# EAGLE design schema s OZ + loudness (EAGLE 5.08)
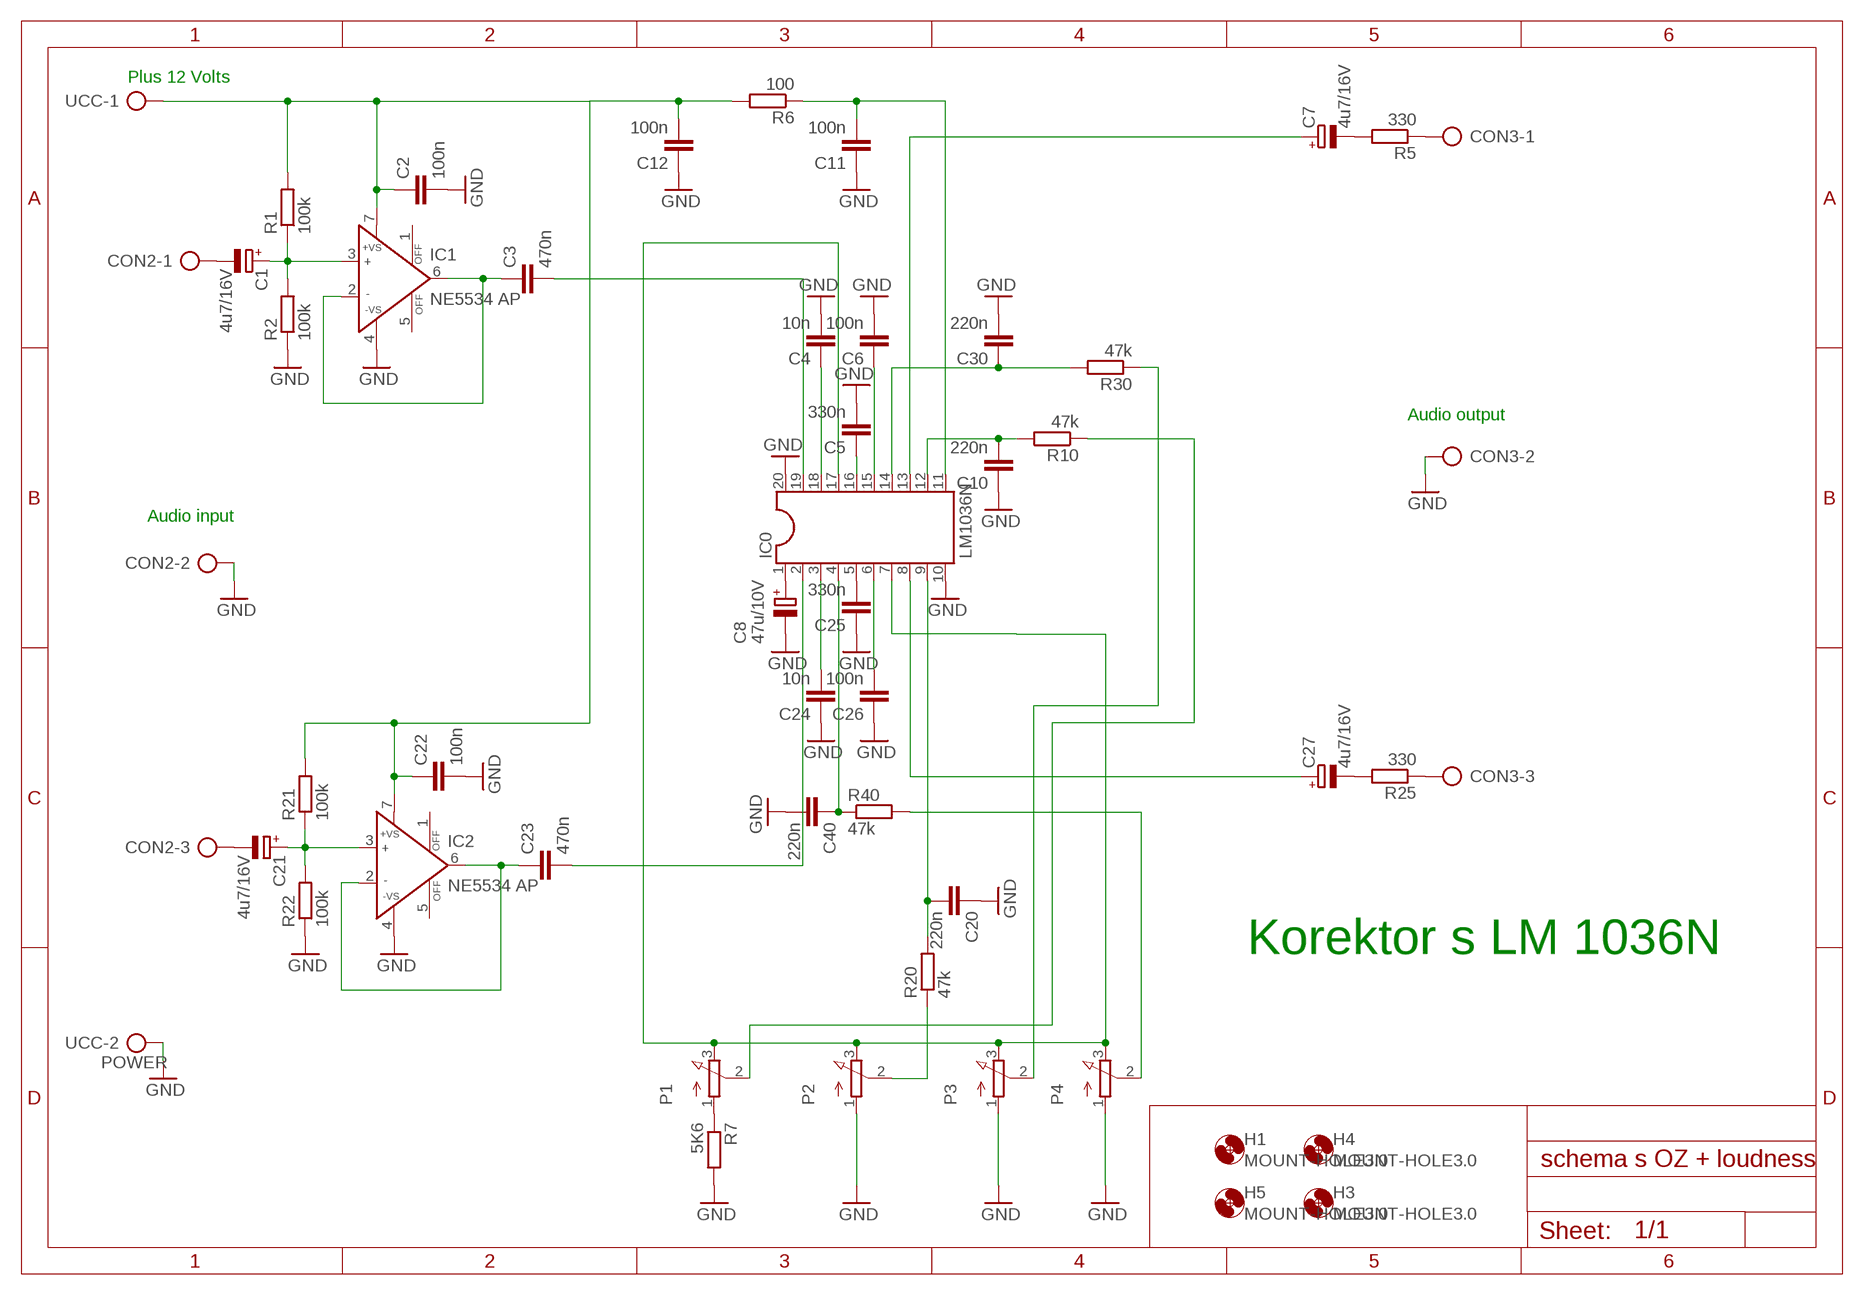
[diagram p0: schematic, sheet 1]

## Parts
C1  4u7/16V  CPOL-EUE2.5-5  [E2,5-5]
C2  100n  C-EU050-025X075  [C050-025X075]
C3  470n  C-EU050-025X075  [C050-025X075]
C4  10n  C-EU050-025X075  [C050-025X075]
C5  330n  C-EU050-025X075  [C050-025X075]
C6  100n  C-EU050-025X075  [C050-025X075]
C7  4u7/16V  CPOL-EUE2.5-5  [E2,5-5]
C8  47u/10V  CPOL-EUE2.5-7  [E2,5-7]
C10  220n  C-EU050-025X075  [C050-025X075]
C11  100n  C-EU050-025X075  [C050-025X075]
C12  100n  C-EU050-025X075  [C050-025X075]
C20  220n  C-EU050-025X075  [C050-025X075]
C21  4u7/16V  CPOL-EUE2.5-5  [E2,5-5]
C22  100n  C-EU050-025X075  [C050-025X075]
C23  470n  C-EU075-032X103  [C075-032X103]
C24  10n  C-EU050-025X075  [C050-025X075]
C25  330n  C-EU050-025X075  [C050-025X075]
C26  100n  C-EU050-025X075  [C050-025X075]
C27  4u7/16V  CPOL-EUE2.5-5  [E2,5-5]
C30  220n  C-EU050-025X075  [C050-025X075]
C40  220n  C-EU050-025X075  [C050-025X075]
CON2  AK500/3  [AK500/3]
CON3  AK500/3  [AK500/3]
H1  MOUNT-HOLE3.0  [3,0]
H3  MOUNT-HOLE3.0  [3,0]
H4  MOUNT-HOLE3.0  [3,0]
H5  MOUNT-HOLE3.0  [3,0]
IC0  LM1036N  DIL20S  [SOCKET-20]
IC1  NE5534 AP  AD711N  [DIL08]
IC2  NE5534 AP  AD711N  [DIL08]
P1  3RP/1610N  [3RP/1610N]
P2  3RP/1610N  [3RP/1610N]
P3  3RP/1610N  [3RP/1610N]
P4  3RP/1610N  [3RP/1610N]
R1  100k  R-EU_0207/10  [0207/10]
R2  100k  R-EU_0207/10  [0207/10]
R5  330  R-EU_0207/10  [0207/10]
R6  100  R-EU_0207/12  [0207/12]
R7  5K6  R-EU_0207/10  [0207/10]
R10  47k  R-EU_0207/12  [0207/12]
R20  47k  R-EU_0207/10  [0207/10]
R21  100k  R-EU_0207/10  [0207/10]
R22  100k  R-EU_0207/10  [0207/10]
R25  330  R-EU_0207/10  [0207/10]
R30  47k  R-EU_0207/12  [0207/12]
R40  47k  R-EU_0207/10  [0207/10]
UCC  POWER  AK500/2  [AK500/2]

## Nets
C25: C26.2 IC0.6
GND: C2.2 C4.2 C5.2 C6.2 C8.- C10.1 C11.1 C12.1 C20.1 C22.2 C24.1 C25.1 C26.1 C30.2 C40.2 CON2.2 CON3.2 IC0.10 IC0.20 IC1.4(-VS) IC2.4(-VS) P2.1(A) P3.1(A) P4.1(A) R2.1 R7.2 R22.1 UCC.2
N$1: C1.- CON2.1
N$2: C3.1 IC1.2(IN-) IC1.6(OUT)
N$3: C23.1 IC2.2(IN-) IC2.6(OUT)
N$4: C1.+ IC1.3(IN+) R1.1 R2.2
N$5: C21.- CON2.3
N$6: C21.+ IC2.3(IN+) R21.1 R22.2
N$7: C2.1 C12.2 C22.1 IC1.7(+VS) IC2.7(+VS) R1.2 R6.2 R21.2 UCC.1
N$8: C3.2 IC0.19
N$9: C23.2 IC0.2
N$10: IC0.17 P1.3(E) P2.3(E) P3.3(E) P4.3(E)
N$11: C11.2 IC0.11 R6.1
N$12: C4.1 IC0.18
N$13: C5.1 IC0.16
N$14: C6.1 IC0.15
N$15: C8.+ IC0.1
N$16: C24.2 IC0.3
N$17: C25.2 IC0.5
N$18: C10.2 IC0.12 R10.2
N$19: P1.1(A) R7.1
N$20: C40.1 IC0.4 R40.1
N$21: P4.2(S) R40.2
N$22: IC0.7
N$23: C7.- R5.2
N$24: C27.- R25.2
N$25: C7.+ IC0.13
N$26: C27.+ IC0.8
N$27: C20.2 IC0.9 R20.2
N$28: P2.2(S) R20.1
N$29: CON3.1 R5.1
N$30: CON3.3 R25.1
N$31: C30.1 IC0.14 R30.2
N$32: P3.2(S) R30.1
N$34: P1.2(S) R10.1
Unconnected: IC1.1(OFF) IC1.5(OFF) IC2.1(OFF) IC2.5(OFF)

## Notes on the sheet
- Plus 12 Volts
- Audio output
- Audio input
- Korektor s LM 1036N

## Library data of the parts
C1 C7 C8 C21 C27 = rcl:CPOL-EU: POLARIZED CAPACITOR, European symbol
C2-C6 C10-C12 C20 C22-C26 C30 C40 = rcl:C-EU: CAPACITOR, European symbol
CON2 CON3 = #Svorkovnice:AK500/3: CONNECTOR
H1 H3-H5 = holes:MOUNT-HOLE: MOUNTING HOLE with drill center marker
IC0 = ic-package:DIL20: Dual In Line / Socket
IC1 IC2 = analog-devices:AD711: Precision, Low Cost, High Speed, BiFET Op Amp Source: http://www.analog.com/static/imported-files/data_sheets/AD711.pdf
P1-P4 = pot:3RP/1610N: 16mm Potentiometer one level Source: http://www.alphapotentiometers.net/html/16mm_pot_2.html
R1 R2 R5-R7 R10 R20-R22 R25 R30 R40 = rcl:R-EU_: RESISTOR, European symbol
UCC = #Svorkovnice:AK500/2: CONNECTOR

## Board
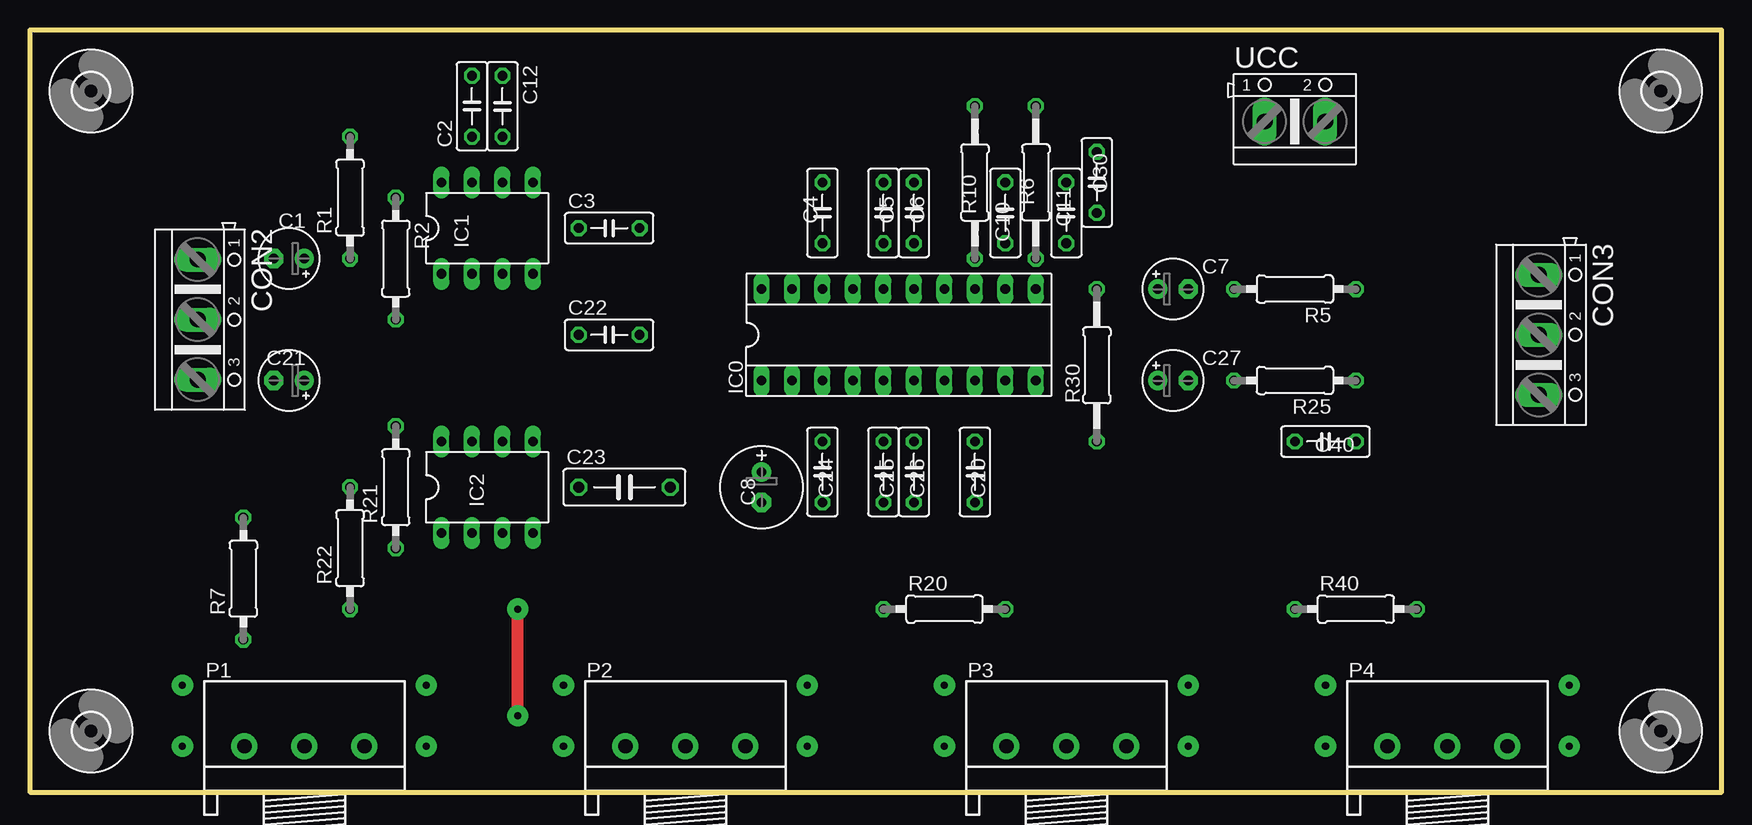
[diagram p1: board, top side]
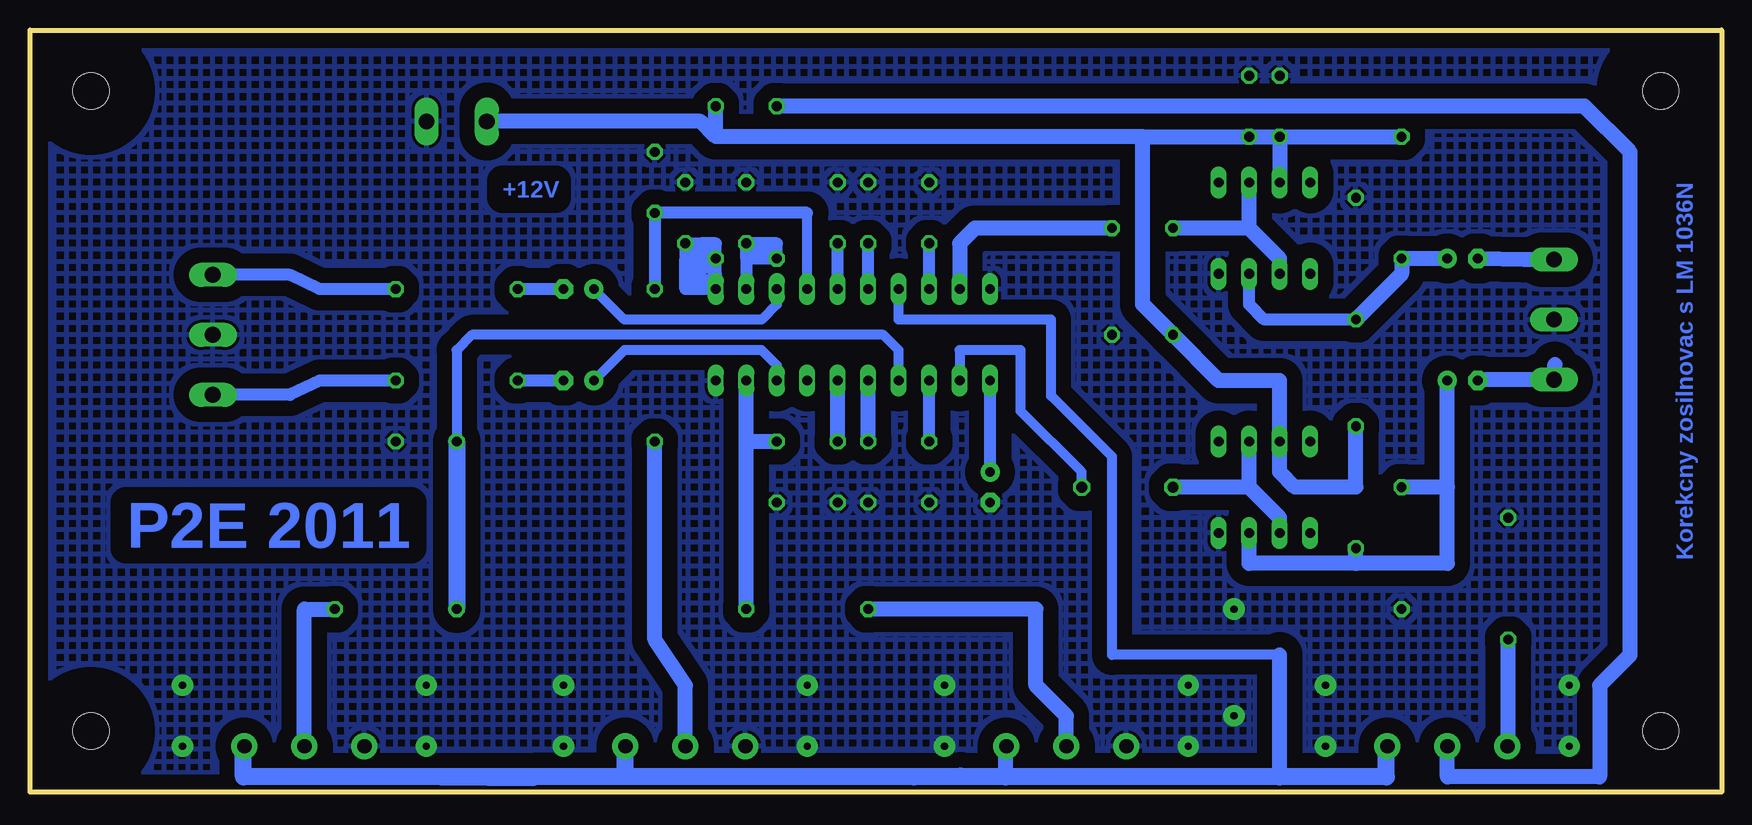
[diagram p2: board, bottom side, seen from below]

Size 140.97 x 63.5 mm. Coordinates in mm from the lower left corner, seen from the top.
Outline: 0,0 140.97,0 140.97,63.5 0,63.5 0,0
Copper layers (1*16): Top 0.035mm / dielectric 1.5mm / Bottom 0.035mm
Design rules "default": minimum track width 10mil, minimum drill 24mil, track to track 8mil, track to pad 8mil, pad to pad 8mil, via to via 8mil, smd to smd 8mil, copper to edge 40mil, drill to drill 8mil, minimum pad ring 10mil, minimum via ring 8mil, stop-mask expansion 4mil, vias tented up to drill 0mil, thermal gap 10mil

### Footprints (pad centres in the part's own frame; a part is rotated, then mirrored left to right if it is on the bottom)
E2,5-5 = drill 0.813 pad 1.6 round: + -1.27,0 | drill 0.813 pad 1.6 octagon: - 1.27,0
C050-025X075 = drill 0.813 octagon: 1 -2.54,0; 2 2.54,0
E2,5-7 = drill 0.813 pad 1.6 round: + -1.27,0 | drill 0.813 pad 1.6 octagon: - 1.27,0
C075-032X103 = drill 0.914 octagon: 1 -3.81,0; 2 3.81,0
AK500/3 = drill 1.321 long: 1 -5.004,0; 2 0,0; 3 5.004,0
3,0 = hole 3: 0,0
SOCKET-20 = drill 0.813 long: 1 -11.43,-3.81; 2 -8.89,-3.81; 3 -6.35,-3.81; 4 -3.81,-3.81; 5 -1.27,-3.81; 6 1.27,-3.81; 7 3.81,-3.81; 8 6.35,-3.81; 9 8.89,-3.81; 10 11.43,-3.81; 11 11.43,3.81; 12 8.89,3.81; 13 6.35,3.81; 14 3.81,3.81; 15 1.27,3.81; 16 -1.27,3.81; 17 -3.81,3.81; 18 -6.35,3.81; 19 -8.89,3.81; 20 -11.43,3.81
DIL08 = drill 0.813 long: 1 -3.81,-3.81; 2 -1.27,-3.81; 3 1.27,-3.81; 4 3.81,-3.81; 5 3.81,3.81; 6 1.27,3.81; 7 -1.27,3.81; 8 -3.81,3.81
3RP/1610N = drill 1.2 pad 2.184 round: 1 -5,0; 2 0,0; 3 5,0
0207/10 = drill 0.813 octagon: 1 -5.08,0; 2 5.08,0
0207/12 = drill 0.813 octagon: 1 -6.35,0; 2 6.35,0
AK500/2 = drill 1.321 long: 1 -2.515,0; 2 2.515,0

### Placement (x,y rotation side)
C1  21.59,44.45 180 top
C2  36.83,57.15 90 top
C3  48.26,46.99 0 top
C4  66.04,48.26 90 top
C5  71.12,48.26 90 top
C6  73.66,48.26 90 top
C7  95.25,41.91 0 top
C8  60.96,25.4 270 top
C10  81.28,48.26 270 top
C11  86.36,48.26 270 top
C12  39.37,57.15 270 top
C20  78.74,26.67 90 top
C21  21.59,34.29 180 top
C22  48.26,38.1 0 top
C23  49.53,25.4 0 top
C24  66.04,26.67 90 top
C25  71.12,26.67 90 top
C26  73.66,26.67 90 top
C27  95.25,34.29 0 top
C30  88.9,50.8 90 top
C40  107.95,29.21 0 top
CON2  13.97,39.37 270 top
CON3  125.73,38.1 270 top
H1  5.08,5.08 0 top
H3  135.89,5.08 0 top
H4  135.89,58.42 0 top
H5  5.08,58.42 0 top
IC0  72.39,38.1 0 top
IC1  38.1,46.99 0 top
IC2  38.1,25.4 0 top
P1  22.86,3.81 0 top
P2  54.61,3.81 0 top
P3  86.36,3.81 0 top
P4  118.11,3.81 0 top
R1  26.67,49.53 90 top
R2  30.48,44.45 270 top
R5  105.41,41.91 180 top
R6  83.82,50.8 90 top
R7  17.78,17.78 90 top
R10  78.74,50.8 270 top
R20  76.2,15.24 0 top
R21  30.48,25.4 90 top
R22  26.67,20.32 90 top
R25  105.41,34.29 180 top
R30  88.9,35.56 90 top
R40  110.49,15.24 0 top
UCC  105.41,55.88 0 top

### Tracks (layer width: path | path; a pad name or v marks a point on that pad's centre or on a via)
C25
  Bottom 1.27: C26.2 IC0.6
GND  (via drill 0.6 pad 1.78)
  Top 1.016: v40.64,6.35 v40.64,15.24
  other vias: 12.7,8.89 12.7,3.81 33.02,8.89 33.02,3.81 44.45,3.81 44.45,8.89 64.77,8.89 64.77,3.81 76.2,3.81 76.2,8.89 96.52,8.89 96.52,3.81 107.95,3.81 107.95,8.89 128.27,8.89 128.27,3.81
  pour Bottom (isolate 1.27, hatched): 0,63.5 0,0 140.97,0 140.97,63.5
N$1
  Bottom 1.27: CON2.1 16.43,44.37 C1.-
N$2
  Bottom 1.27: IC1.2 36.83,44.45 39.37,46.99 | 39.37,46.99 IC1.6 | 39.37,46.99 C3.1
N$3
  Bottom 1.27: IC2.2 36.83,22.86 39.37,25.4 | 39.37,25.4 IC2.6 | 39.37,25.4 C23.1
N$4
  Bottom 1.016: IC1.3 39.37,40.64 38.1,39.37 R2.2
  Bottom 1.27: C1.+ R1.1 26.67,43.18 R2.2
N$5
  Bottom 1.27: 13.89,35.64 CON2.3 20.32,34.37 C21.-
N$6
  Bottom 1.27: IC2.3 39.37,19.05 30.48,19.05 | 30.48,19.05 R21.1 | 30.48,19.05 22.86,19.05 22.86,25.4 | 22.86,25.4 C21.+ | 22.86,25.4 R22.2
N$7
  Bottom 1.27: C2.1 C12.2 48.26,54.61 | C2.1 R1.2 | C2.1 IC1.7 | 48.26,54.61 48.26,40.64 C22.1 41.91,34.29 36.83,34.29 IC2.7 36.83,26.67 35.56,25.4 30.48,25.4 R21.2 | 48.26,54.61 83.82,54.61 | UCC.1 85.09,55.88 83.82,54.61 | 83.82,54.61 R6.2
N$8
  Bottom 1.27: C3.2 62.23,46.99 63.5,45.72 IC0.19
N$9
  Bottom 0.813: IC0.2 63.5,36.83 58.42,36.83 58.42,31.75 53.34,26.67 C23.2
N$10
  Bottom 0.813: IC0.17 68.58,39.37 55.88,39.37 55.88,33.02 50.8,27.94 50.8,11.43 36.83,11.43
  Bottom 1.27: 59.69,1.27 P2.3 | 27.94,3.81 P1.3 | 123.19,3.73 P4.3 | 36.83,1.27 36.83,11.43
  Bottom 1.422: 27.94,3.81 27.94,1.27 36.83,1.27 59.69,1.27 67.31,1.27 | 67.31,1.27 63.42,1.35 | 67.31,1.27 106.68,1.27 | 106.68,1.27 99.06,1.19 | P3.3 91.36,1.35 106.68,1.27 | 106.68,1.27 123.19,1.27 123.19,3.73
N$11
  Bottom 1.016: 83.82,43.18 IC0.11 85.09,41.91 | 83.82,43.18 R6.1 83.82,45.72 | C11.2 85.09,45.72 | 86.36,41.91 86.36,43.18 | 86.36,43.18 86.36,44.45 | C11.2 86.36,44.45 | 85.09,44.45 C11.2 | 83.82,43.18 85.09,44.45 | 83.82,43.18 85.09,41.91 | 85.09,41.91 86.36,41.91 | 86.36,41.91 85.09,43.18 | 86.36,43.18 85.09,43.18 | 85.09,44.45 86.36,43.18 | 85.09,44.45 83.82,45.72 | 83.82,45.72 85.09,45.72 | 86.36,44.45 85.09,45.72 | 85.09,43.18 86.36,44.45
N$12
  Bottom 1.016: IC0.18 C4.1
N$13
  Bottom 1.016: IC0.16 C5.1
N$14
  Bottom 1.016: IC0.15 C6.1
N$15
  Bottom 1.016: C8.+ IC0.1
N$16
  Bottom 1.016: C24.2 IC0.3
N$17
  Bottom 1.27: C25.2 IC0.5
N$18
  Bottom 1.016: 81.28,44.45 IC0.12 | 80.01,44.45 R10.2 78.74,45.72 | 78.74,45.72 80.01,45.72 | 80.01,45.72 C10.2 81.28,44.45 | 80.01,44.45 78.74,45.72 | 80.01,44.45 81.28,44.45 | 80.01,45.72 81.28,44.45
N$19
  Bottom 1.27: R7.1 17.78,3.81 P1.1
N$20
  Bottom 0.813: C40.1 105.41,36.83 104.14,38.1 69.85,38.1 68.58,36.83 IC0.4
  Bottom 1.422: C40.1 R40.1
N$21
  Bottom 1.27: R40.2 118.11,15.24 P4.2
N$23
  Bottom 1.016: C7.- R5.2
N$24
  Bottom 1.016: C27.- R25.2
N$25
  Bottom 0.813: IC0.13 78.74,40.64 80.01,39.37 91.44,39.37 C7.+
N$26
  Bottom 0.813: C27.+ 91.44,36.83 80.01,36.83 78.74,35.56 IC0.8
N$27
  Bottom 1.27: 81.28,29.21 C20.2 | 81.28,29.21 IC0.9 | R20.2 81.28,29.21
N$28
  Bottom 1.27: R20.1 57.15,15.24 57.15,8.89 54.61,6.35 P2.2
N$29
  Bottom 1.016: CON3.1 119.3,43.1 116.84,41.91 R5.1
N$30
  Bottom 1.016: CON3.3 119.3,33.1 116.84,34.29 R25.1
N$31
  Bottom 0.813: IC0.14 76.2,48.26
  Bottom 1.016: 76.2,48.26 C30.1 R30.2
N$32
  Bottom 1.27: R30.1 88.9,12.7 86.36,8.89 P3.2
N$34
  Bottom 1.27: R10.1 11.43,57.15 7.62,53.34 7.62,11.43 10.16,8.89 10.16,1.27 22.86,1.27 P1.2

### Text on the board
Bottom: Korekcny zosilnovac s LM 1036N | +12V | P2E 2011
